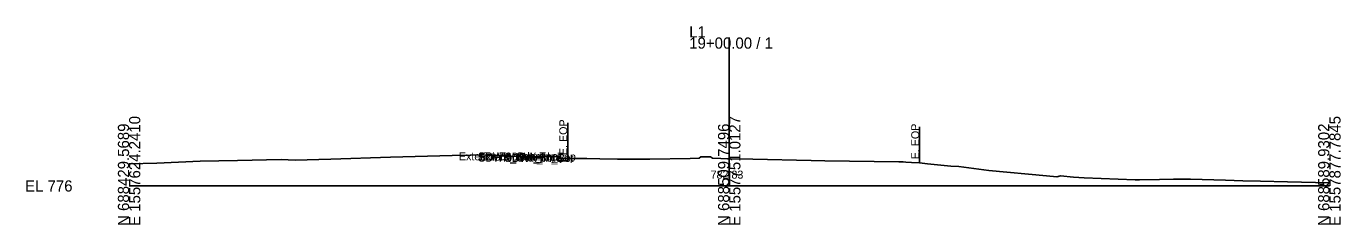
# Model space of a CAD drawing. Extents: x -26 to 2603, y -3010 to 9589.
# Drawn here: x -25.7 to 302.8, y 2490.3 to 2539.9 of the extents above; entities that cross this region are included whole.
import ezdxf

# ---------------------------------------------------------------- set-up
doc = ezdxf.new("R2010")
doc.units = 0
for name, color, linetype in [('Default', 7, 'Continuous'), ('Exist Cross Section Cell', 7, 'Continuous'), ('Exist XS Center Line Elevation Label', 7, 'Continuous'), ('Exist XS Ground Line', 7, 'Continuous'), ('Prop CMT Conc Surface', 7, 'Continuous'), ('Prop CMT Concrete Structures', 7, 'Continuous'), ('Prop XS Earthwork Shape', 7, 'Continuous'), ('Prop XS Label Text', 7, 'Continuous')]:
    doc.layers.add(name, color=color, linetype=linetype)

msp = doc.modelspace()

# ---------------------------------------------------------------- linework, layer by layer
at = {"layer": 'Exist Cross Section Cell'}
for p, q in [((150, 2500), (150, 2537.12)), ((0, 2500), (150, 2500)), ((150, 2500), (300, 2500))]:
    msp.add_line(p, q, dxfattribs=at)
at = {"layer": 'Exist XS Ground Line'}
msp.add_lwpolyline([(0, 2505.51), (6.96, 2505.73), (17.8, 2506.17), (27.13, 2506.35), (38.02, 2506.64), (41.51, 2506.48), (50.46, 2506.68), (65.35, 2507.17), (80.76, 2507.6), (85.4, 2507.67), (87.93, 2507.82), (90.71, 2507.62), (95.5, 2507.42), (107.16, 2507.26), (107.47, 2507.04), (107.88, 2506.77), (109.08, 2506.83), (109.66, 2506.88), (114.42, 2506.84), (117.7, 2506.75), (122.1, 2506.73), (130.2, 2506.71), (140.2, 2506.87), (142.5, 2506.91), (142.94, 2507.31), (144.58, 2507.29), (145.33, 2507.32), (145.81, 2506.93), (150, 2506.81), (155.93, 2506.66), (170.47, 2506.36), (173.89, 2506.26), (192.43, 2506.04), (193.49, 2506.02), (194.13, 2505.98), (195.58, 2505.87), (197.6, 2505.74), (199.56, 2505.57), (205.4, 2504.92), (207.4, 2504.84), (214.89, 2503.83), (229.34, 2502.5), (231.85, 2502.32), (232.77, 2502.49), (236.05, 2502.22), (238.73, 2502.06), (251.48, 2501.5), (252.57, 2501.49), (257.52, 2501.62), (261.01, 2501.72), (261.48, 2501.71), (265.3, 2501.66), (274.01, 2501.44), (278.34, 2501.25), (282.8, 2501.2), (289.58, 2500.99), (300, 2500.77)], dxfattribs=at)
at = {"layer": 'Prop CMT Conc Surface'}
msp.add_line((103.29, 2507.31), (98.29, 2507.38), dxfattribs=at)
for points in [[(107.63, 2506.76), (107.63, 2507.26), (107.13, 2507.26)], [(109.63, 2506.88), (107.63, 2506.76)]]:
    msp.add_lwpolyline(points, dxfattribs=at)
at = {"layer": 'Prop CMT Concrete Structures'}
msp.add_line((103.29, 2506.98), (98.29, 2507.05), dxfattribs=at)
for points in [[(98.29, 2507.05), (98.29, 2507.38)], [(103.29, 2507.31), (103.29, 2506.98)], [(107.13, 2507.26), (107.13, 2506.25), (109.63, 2506.3)], [(109.63, 2506.3), (109.63, 2506.88)]]:
    msp.add_lwpolyline(points, dxfattribs=at)
at = {"layer": 'Prop XS Earthwork Shape'}
msp.add_lwpolyline([(103.29, 2507.31), (103.29, 2506.98), (98.29, 2507.05), (98.29, 2507.38)], close=True, dxfattribs=at)
at = {"layer": 'Prop XS Label Text'}
for p, q in [((109.63, 2515.79), (109.63, 2506.79)), ((197.6, 2514.74), (197.6, 2505.74))]:
    msp.add_line(p, q, dxfattribs=at)

# ---------------------------------------------------------------- texts
at = {"layer": 'Default'}
for s, height, p in [('Exterior Boundary', 2, (82.43, 2506.41)), ('SDWK_Out_Top', 2, (87.22, 2506.41)), ('SDWK_Out_Bot', 2, (87.25, 2506.08)), ('Exterior Boundary', 2, (87.43, 2506.31)), ('SDWK_In_Top', 2, (93.84, 2506.31)), ('SDWK_In_Bot', 2, (93.87, 2505.98)), ('-', 0.0001, (0, 2500))]:
    msp.add_text(s, height=height, dxfattribs=at).set_placement(p)
at = {"layer": 'Exist Cross Section Cell'}
for s, p in [('L1', (140, 2537.12)), ('19+00.00 / 1', (140, 2534.32)), ('EL 776', (-26, 2498.6))]:
    msp.add_text(s, height=2.8, dxfattribs=at).set_placement(p)
for s, p in [('E 1557624.2410', (2.8, 2490)), ('E 1557751.0127', (152.8, 2490)), ('E 1557877.7845', (302.8, 2490)), ('N 688429.5689', (0, 2490)), ('N 688509.7496', (150, 2490)), ('N 688589.9302', (300, 2490))]:
    msp.add_text(s, height=2.8, rotation=90, dxfattribs=at).set_placement(p)
at = {"layer": 'Exist XS Center Line Elevation Label'}
msp.add_text('782.83', height=2, dxfattribs=at).set_placement((145.35, 2501.83))
at = {"layer": 'Prop XS Label Text'}
for p in [(109.53, 2507.72), (197.5, 2506.66)]:
    msp.add_text('E. EOP', height=2, rotation=90, dxfattribs=at).set_placement(p)

doc.saveas('drawing.dxf')
